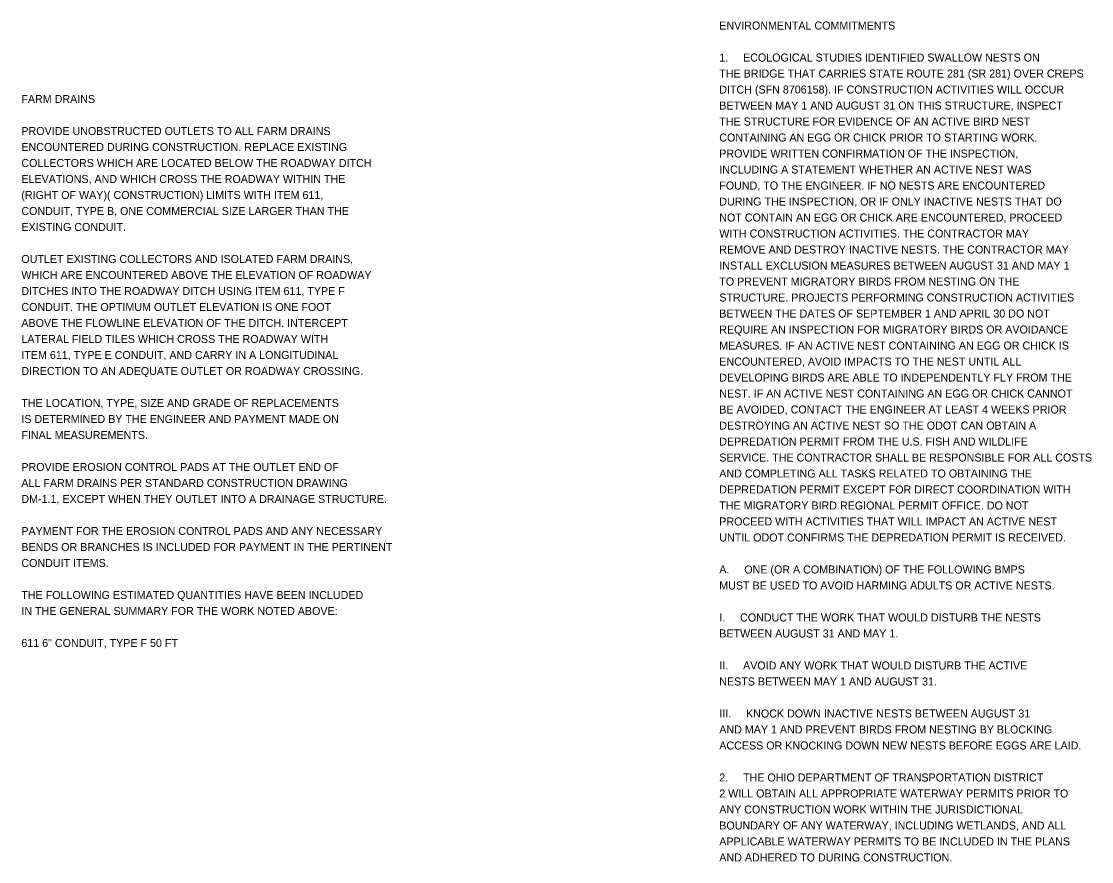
# Model space of a CAD drawing. Extents: x -24.6 to 58.4, y 0 to 22.8.
# Drawn here: x 39.72 to 58.45, y 0.72 to 15.43 of the extents above; entities that cross this region are included whole.
import ezdxf

# ---------------------------------------------------------------- set-up
doc = ezdxf.new("R2010")
doc.units = 0
doc.layers.add('SH_Text', color=7, linetype='Continuous')

msp = doc.modelspace()

# ---------------------------------------------------------------- texts
at = {"layer": 'SH_Text'}
for s, p in [('ENVIRONMENTAL COMMITMENTS', (51.931, 15.286)), ('1.     ECOLOGICAL STUDIES IDENTIFIED SWALLOW NESTS ON', (51.931, 14.726)), ('THE BRIDGE THAT CARRIES STATE ROUTE 281 (SR 281) OVER CREPS', (51.931, 14.446)), ('DITCH (SFN 8706158). IF CONSTRUCTION ACTIVITIES WILL OCCUR', (51.931, 14.166)), ('FARM DRAINS', (39.72, 14)), ('BETWEEN MAY 1 AND AUGUST 31 ON THIS STRUCTURE, INSPECT', (51.931, 13.886)), ('THE STRUCTURE FOR EVIDENCE OF AN ACTIVE BIRD NEST', (51.931, 13.606)), ('PROVIDE UNOBSTRUCTED OUTLETS TO ALL FARM DRAINS', (39.72, 13.44)), ('ENCOUNTERED DURING CONSTRUCTION. REPLACE EXISTING', (39.72, 13.16)), ('CONTAINING AN EGG OR CHICK PRIOR TO STARTING WORK.', (51.931, 13.326)), ('PROVIDE WRITTEN CONFIRMATION OF THE INSPECTION,', (51.931, 13.046)), ('COLLECTORS WHICH ARE LOCATED BELOW THE ROADWAY DITCH', (39.72, 12.88)), ('ELEVATIONS, AND WHICH CROSS THE ROADWAY WITHIN THE', (39.72, 12.6)), ('INCLUDING A STATEMENT WHETHER AN ACTIVE NEST WAS', (51.931, 12.766)), ('FOUND, TO THE ENGINEER. IF NO NESTS ARE ENCOUNTERED', (51.931, 12.486)), ('(RIGHT OF WAY)( CONSTRUCTION) LIMITS WITH ITEM 611,', (39.72, 12.32)), ('CONDUIT, TYPE B, ONE COMMERCIAL SIZE LARGER THAN THE', (39.72, 12.04)), ('DURING THE INSPECTION, OR IF ONLY INACTIVE NESTS THAT DO', (51.931, 12.206)), ('NOT CONTAIN AN EGG OR CHICK ARE ENCOUNTERED, PROCEED', (51.931, 11.926)), ('EXISTING CONDUIT.', (39.72, 11.76)), ('WITH CONSTRUCTION ACTIVITIES. THE CONTRACTOR MAY', (51.931, 11.646)), ('REMOVE AND DESTROY INACTIVE NESTS. THE CONTRACTOR MAY', (51.931, 11.366)), ('OUTLET EXISTING COLLECTORS AND ISOLATED FARM DRAINS,', (39.72, 11.2)), ('WHICH ARE ENCOUNTERED ABOVE THE ELEVATION OF ROADWAY', (39.72, 10.92)), ('INSTALL EXCLUSION MEASURES BETWEEN AUGUST 31 AND MAY 1', (51.931, 11.086)), ('TO PREVENT MIGRATORY BIRDS FROM NESTING ON THE', (51.931, 10.806)), ('DITCHES INTO THE ROADWAY DITCH USING ITEM 611, TYPE F', (39.72, 10.64)), ('CONDUIT. THE OPTIMUM OUTLET ELEVATION IS ONE FOOT', (39.72, 10.36)), ('STRUCTURE. PROJECTS PERFORMING CONSTRUCTION ACTIVITIES', (51.931, 10.526)), ('BETWEEN THE DATES OF SEPTEMBER 1 AND APRIL 30 DO NOT', (51.931, 10.246)), ('ABOVE THE FLOWLINE ELEVATION OF THE DITCH. INTERCEPT', (39.72, 10.08)), ('LATERAL FIELD TILES WHICH CROSS THE ROADWAY WITH', (39.72, 9.8)), ('REQUIRE AN INSPECTION FOR MIGRATORY BIRDS OR AVOIDANCE', (51.931, 9.966)), ('MEASURES. IF AN ACTIVE NEST CONTAINING AN EGG OR CHICK IS', (51.931, 9.686)), ('ITEM 611, TYPE E CONDUIT, AND CARRY IN A LONGITUDINAL', (39.72, 9.52)), ('DIRECTION TO AN ADEQUATE OUTLET OR ROADWAY CROSSING.', (39.72, 9.24)), ('ENCOUNTERED, AVOID IMPACTS TO THE NEST UNTIL ALL', (51.931, 9.406)), ('DEVELOPING BIRDS ARE ABLE TO INDEPENDENTLY FLY FROM THE', (51.931, 9.126)), ('NEST. IF AN ACTIVE NEST CONTAINING AN EGG OR CHICK CANNOT', (51.931, 8.846)), ('THE LOCATION, TYPE, SIZE AND GRADE OF REPLACEMENTS', (39.72, 8.68)), ('BE AVOIDED, CONTACT THE ENGINEER AT LEAST 4 WEEKS PRIOR', (51.931, 8.566)), ('IS DETERMINED BY THE ENGINEER AND PAYMENT MADE ON', (39.72, 8.4)), ('DESTROYING AN ACTIVE NEST SO THE ODOT CAN OBTAIN A', (51.931, 8.286)), ('FINAL MEASUREMENTS.', (39.72, 8.12)), ('DEPREDATION PERMIT FROM THE U.S. FISH AND WILDLIFE', (51.931, 8.006)), ('SERVICE. THE CONTRACTOR SHALL BE RESPONSIBLE FOR ALL COSTS', (51.931, 7.726)), ('PROVIDE EROSION CONTROL PADS AT THE OUTLET END OF', (39.72, 7.56)), ('AND COMPLETING ALL TASKS RELATED TO OBTAINING THE', (51.931, 7.446)), ('ALL FARM DRAINS PER STANDARD CONSTRUCTION DRAWING', (39.72, 7.28)), ('DEPREDATION PERMIT EXCEPT FOR DIRECT COORDINATION WITH', (51.931, 7.166)), ('DM-1.1, EXCEPT WHEN THEY OUTLET INTO A DRAINAGE STRUCTURE.', (39.72, 7)), ('THE MIGRATORY BIRD REGIONAL PERMIT OFFICE. DO NOT', (51.931, 6.886)), ('PROCEED WITH ACTIVITIES THAT WILL IMPACT AN ACTIVE NEST', (51.931, 6.606)), ('PAYMENT FOR THE EROSION CONTROL PADS AND ANY NECESSARY', (39.72, 6.44)), ('UNTIL ODOT CONFIRMS THE DEPREDATION PERMIT IS RECEIVED.', (51.931, 6.326)), ('BENDS OR BRANCHES IS INCLUDED FOR PAYMENT IN THE PERTINENT', (39.72, 6.16)), ('CONDUIT ITEMS.', (39.72, 5.88)), ('A.     ONE (OR A COMBINATION) OF THE FOLLOWING BMPS', (51.931, 5.766)), ('MUST BE USED TO AVOID HARMING ADULTS OR ACTIVE NESTS.', (51.931, 5.486)), ('THE FOLLOWING ESTIMATED QUANTITIES HAVE BEEN INCLUDED', (39.72, 5.32)), ('IN THE GENERAL SUMMARY FOR THE WORK NOTED ABOVE:', (39.72, 5.04)), ('I.     CONDUCT THE WORK THAT WOULD DISTURB THE NESTS', (51.931, 4.926)), ('BETWEEN AUGUST 31 AND MAY 1.', (51.931, 4.646)), ('611 6" CONDUIT, TYPE F 50 FT', (39.72, 4.48)), ('II.     AVOID ANY WORK THAT WOULD DISTURB THE ACTIVE', (51.931, 4.086)), ('NESTS BETWEEN MAY 1 AND AUGUST 31.', (51.931, 3.806)), ('III.     KNOCK DOWN INACTIVE NESTS BETWEEN AUGUST 31', (51.931, 3.246)), ('AND MAY 1 AND PREVENT BIRDS FROM NESTING BY BLOCKING', (51.931, 2.966)), ('ACCESS OR KNOCKING DOWN NEW NESTS BEFORE EGGS ARE LAID.', (51.931, 2.686)), ('2.     THE OHIO DEPARTMENT OF TRANSPORTATION DISTRICT', (51.931, 2.126)), ('2 WILL OBTAIN ALL APPROPRIATE WATERWAY PERMITS PRIOR TO', (51.931, 1.846)), ('ANY CONSTRUCTION WORK WITHIN THE JURISDICTIONAL', (51.931, 1.566)), ('BOUNDARY OF ANY WATERWAY, INCLUDING WETLANDS, AND ALL', (51.931, 1.286)), ('APPLICABLE WATERWAY PERMITS TO BE INCLUDED IN THE PLANS', (51.931, 1.006)), ('AND ADHERED TO DURING CONSTRUCTION.', (51.931, 0.726))]:
    msp.add_text(s, height=0.14, dxfattribs=at).set_placement(p)

doc.saveas('drawing.dxf')
